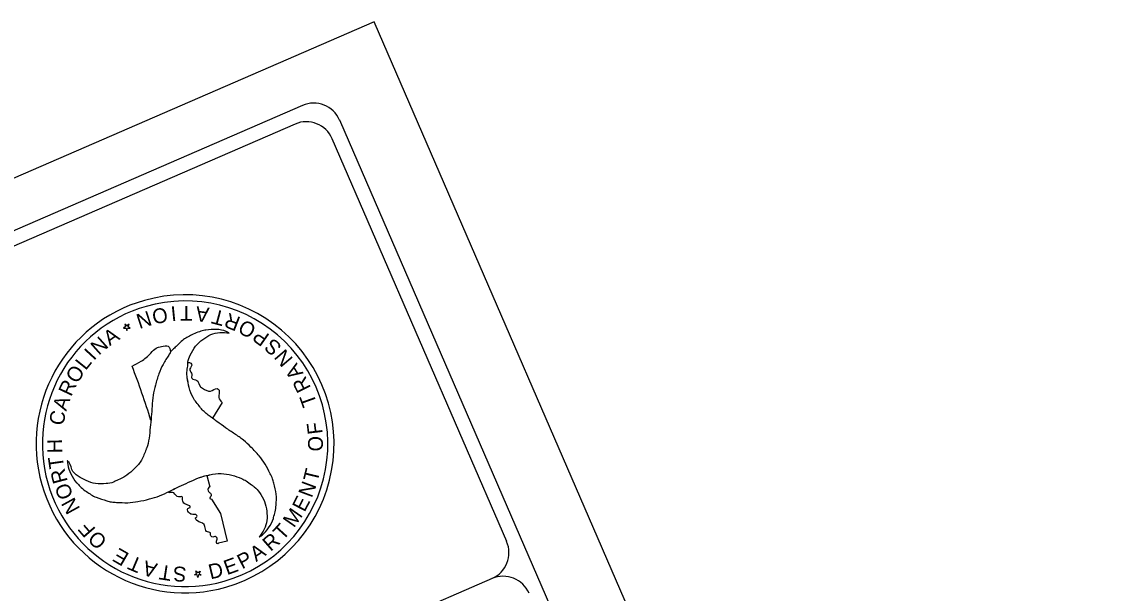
# Model space of a CAD drawing. Extents: x 442728 to 492797, y 479541 to 511293.
# Drawn here: x 478444 to 484269, y 508264 to 511293 of the extents above; entities that cross this region are included whole.
import ezdxf

# ---------------------------------------------------------------- set-up
doc = ezdxf.new("R2010")
doc.units = 0
doc.layers.add('Sheet Plot Border Outside CELL', color=7, linetype='Continuous')
doc.layers.add('Sheet Title CELL', color=7, linetype='Continuous')

msp = doc.modelspace()

# ---------------------------------------------------------------- linework, layer by layer
at = {"layer": 'Sheet Plot Border Outside CELL'}
msp.add_lwpolyline([(465175.4, 504729.3), (475224.7, 481554), (490362.8, 488118.1), (480313.5, 511293.4)], close=True, dxfattribs=at)
at = {"layer": 'Sheet Title CELL'}
for p, q in [((479093.7, 509815.9), (479093.7, 509815.9)), ((479001.2, 509681.9), (478990.1, 509690.2)), ((478990.1, 509690.2), (478994.2, 509677.5)), ((479012.7, 509689.4), (479001.2, 509681.9)), ((479008.1, 509676.6), (479012.7, 509689.4)), ((478994.2, 509677.5), (478983.3, 509669.5)), ((478983.3, 509669.5), (478996.6, 509668.9)), ((478996.6, 509668.9), (479000.3, 509655.9)), ((479000.3, 509655.9), (479004.9, 509668.9)), ((479004.9, 509668.9), (479018.6, 509668.6)), ((479018.6, 509668.6), (479008.1, 509676.6)), ((479506.3, 509274.6), (479455.2, 509191.1)), ((479128.5, 509178.9), (479128.5, 509178.9)), ((479455.2, 509191.1), (479455.2, 509191.1)), ((478684.5, 508964.8), (478686.5, 508963.9)), ((478684.5, 508964.8), (478686.5, 508963.9)), ((479425.4, 508888), (479441.8, 508827.7)), ((479450.4, 508761.4), (479498.3, 508685.6)), ((479498.3, 508685.6), (479533.8, 508539.7)), ((479533.8, 508539.7), (479487.6, 508528.3)), ((480940, 508340.4), (478738.1, 507385.7)), ((479360, 508360), (479370.9, 508368)), ((479373.2, 508359.8), (479360, 508360)), ((479370.9, 508368), (479367.2, 508381)), ((479367.2, 508381), (479378.2, 508372.5)), ((479377, 508346.5), (479373.2, 508359.8)), ((479381.9, 508359.4), (479377, 508346.5)), ((479378.2, 508372.5), (479389.6, 508380.1)), ((479395.6, 508359.1), (479381.9, 508359.4)), ((479389.6, 508380.1), (479384.8, 508367)), ((479384.8, 508367), (479395.6, 508359.1))]:
    msp.add_line(p, q, dxfattribs=at)
for points in [[(479933.3, 510850.6), (465758.6, 504704.2)], [(479894.3, 510752), (477692.4, 509797.2)], [(488962.7, 490404.9), (480130.8, 510772.7)], [(481017.9, 508537.8), (480091.6, 510674)]]:
    msp.add_lwpolyline(points, dxfattribs=at)
for centre, radius, start, end in [((479992.4, 510712.8), 150, 23.44243, 113.44243), ((479953.4, 510614.1), 150, 23.44243, 113.44243), ((479310, 509055.4), 790.8, 105.86356, 285.86356), ((479310, 509055.4), 790.8, 285.86356, 105.86356), ((479310, 509055.4), 757.8, 285.86356, 105.86356), ((479310, 509055.4), 757.8, 105.86356, 285.86356), ((475141.1, 507961.2), 4169.2, 16.98111, 21.18712), ((475141.1, 507961.2), 4169.2, 11.54205, 11.64165), ((480879.5, 508477.8), 150, 293.44243, 23.44243), ((480998.9, 508202.5), 150, 23.44243, 113.44243)]:
    msp.add_arc(centre, radius, start, end, dxfattribs=at)
for points in [[(479543.5, 509642.6), (479528, 509650.9), (479476.4, 509662), (479420.3, 509658.5), (479415, 509657.7), (479385.8, 509649.9), (479352.8, 509636.4), (479301.2, 509608.1), (479257.7, 509567.2), (479239.4, 509550.1), (479223.5, 509526.5), (479193, 509476.9), (479170.8, 509427), (479152.4, 509366.7), (479140.2, 509312.8), (479134.6, 509255.4), (479130.4, 509198.2), (479124.8, 509143), (479118.4, 509084.9), (479104.9, 509030.6), (479103, 509026), (479078.7, 508969.3), (479042, 508924.3), (479001.2, 508888.8), (478978.2, 508874.5), (478947.2, 508860.8), (478929.7, 508852.2), (478890.6, 508844), (478834.6, 508844.7), (478784.6, 508860.4), (478742.2, 508883.7), (478708.5, 508919.7), (478686.5, 508963.9), (478684.5, 508964.8)], [(479702.7, 508560.4), (479718.3, 508570.7), (479753.5, 508609.7), (479778.7, 508659.8), (479779.8, 508664.7), (479788.7, 508694.3), (479792.9, 508729.1), (479794.1, 508788.4), (479780.6, 508846), (479774.9, 508870.4), (479762.1, 508896.7), (479734.6, 508946.9), (479702.9, 508991), (479659.6, 509037.7), (479619.5, 509075), (479572.3, 509108.4), (479524.4, 509140.6), (479479.2, 509173.6), (479433.1, 509208), (479392.1, 509246.8), (479388.6, 509251.4), (479352.3, 509300.5), (479331.7, 509354.1), (479321.6, 509406.8), (479319.6, 509435.2), (479324.2, 509467.9), (479325.1, 509487.9), (479337.5, 509525.8), (479366.1, 509573.2), (479404.7, 509609), (479446.4, 509634.5), (479494.2, 509645.6), (479543.5, 509642.6)], [(479028.6, 509468), (479076.2, 509493.2), (479128.4, 509536.8), (479156.3, 509563.2), (479184.6, 509570.8), (479220, 509573.8), (479232.6, 509542.3)], [(479232.9, 509542.1), (479223.5, 509526.5), (479193, 509476.9), (479170.8, 509427), (479152.4, 509366.7), (479140.2, 509312.8), (479134.6, 509255.4), (479130.4, 509198.2), (479128.5, 509178.9)], [(479455.2, 509191.1), (479433.1, 509208), (479392.1, 509246.8), (479388.6, 509251.4), (479352.3, 509300.5), (479331.7, 509354.1), (479321.6, 509406.8), (479319.6, 509435.2), (479324.2, 509467.9), (479325.2, 509486.5)], [(479325.5, 509486.4), (479340.8, 509483.1), (479345, 509471.9), (479334.7, 509447.3), (479346.6, 509424.1), (479343.3, 509411), (479345.2, 509403.5), (479372.5, 509392), (479384.9, 509369.2), (479425.2, 509338), (479444.4, 509334.7), (479480.1, 509348), (479490, 509340.4), (479491.6, 509328.1), (479489, 509301.1), (479506.3, 509274.6)], [(478686.5, 508963.9), (478686.8, 508945.5), (478703.2, 508895.5), (478734.3, 508848.8), (478738.1, 508845), (478758.9, 508823.2), (478786.9, 508801.6), (478837.7, 508771.5), (478894.6, 508753.6), (478918.7, 508746.8), (478946.6, 508744.7), (479005.1, 508743), (479059.4, 508749), (479121, 508762.8), (479174, 508778.8), (479225.8, 508803.1), (479277.9, 508828.1), (479328.9, 508851.1), (479381.6, 508874.1), (479435.8, 508889.8), (479440.6, 508890.9), (479501.3, 508897.7), (479558.7, 508888.7), (479609.9, 508870.6), (479634.6, 508858.3), (479661.7, 508838.5), (479677.3, 508827.3), (479704.7, 508797.8), (479731.6, 508749.2), (479743.2, 508697.4), (479744.5, 508649.1), (479730.3, 508602.1), (479702.7, 508560.4)], [(479224.5, 508802.5), (479225.8, 508803.1), (479277.9, 508828.1), (479328.9, 508851.1), (479381.6, 508874.1), (479425.4, 508887.8)], [(479441.8, 508827.7), (479432.4, 508818.7), (479432.4, 508806), (479445.2, 508792.6), (479447.9, 508780.4), (479442.2, 508764.6), (479450.4, 508761.4)], [(479487.6, 508528.3), (479483.8, 508525.5), (479476.7, 508531.8), (479479.4, 508555.7), (479467, 508563.9), (479457.9, 508560.8), (479446.3, 508566.7), (479445, 508582.2), (479424.3, 508590.7), (479417.9, 508602.1), (479410.6, 508627.8), (479371.3, 508649.5), (479365.9, 508661.8), (479373.1, 508667.3), (479372.4, 508675.6), (479343.5, 508681.5), (479338.9, 508683.9), (479322.6, 508705.1), (479325.3, 508712.7), (479336.1, 508717.7), (479337.4, 508721.7), (479329.5, 508728), (479313, 508734.8), (479297.3, 508751.5), (479293.6, 508774.6), (479274.3, 508773.2), (479249.3, 508794.4), (479237.1, 508796.8), (479225.9, 508795.1)]]:
    msp.add_spline(points, degree=3, dxfattribs=at)

# ---------------------------------------------------------------- texts
for s, height, rotation, p in [('N', 78.9, 198.07169, (479115.7, 509762.5)), ('O', 78.6, 190.82368, (479209.1, 509781.2)), ('I', 79, 185.68805, (479259.4, 509786.8)), ('T', 78.7, 180.03814, (479348.4, 509787.2)), ('A', 79, 172.95372, (479441.3, 509776.8)), ('T', 78.6, 164.86668, (479528, 509754.9)), ('R', 79, 158.76689, (479609.7, 509724.3)), ('O', 79, 151.57778, (479693.9, 509679.5)), ('N', 78.8, 41.7589, (478852.1, 509521.6)), ('A', 78.9, 34.32692, (478910.1, 509572.7)), ('P', 78.8, 144.88579, (479763.3, 509631.5)), ('I', 79, 47.459, (478825.6, 509493.7)), ('S', 78.5, 137.69394, (479828.1, 509573.1)), ('L', 78.6, 51.44834, (478782, 509441.3)), ('N', 78.6, 130.48347, (479887.3, 509506.4)), ('O', 79, 57.68202, (478737.2, 509370.3)), ('A', 78.6, 123.45184, (479939.9, 509429.5)), ('R', 78.8, 64.80162, (478704.9, 509302.2)), ('R', 78.9, 116.69871, (479980.1, 509352.2)), ('A', 78.8, 71.16557, (478678.9, 509225.6)), ('T', 78.6, 109.74209, (480011.2, 509268.4)), ('C', 78.6, 78.6626, (478663, 509148.5)), ('F', 78.8, 96.83286, (480040.7, 509109.9)), ('H', 78.7, 91.00495, (478658.2, 509005.8)), ('O', 78.8, 89.66763, (480041.4, 509014.6)), ('T', 79, 98.08967, (478668.5, 508929.3)), ('R', 78.9, 104.7393, (478687.8, 508856.3)), ('T', 78.7, 76.36394, (480012.8, 508848.8)), ('O', 79, 111.34923, (478718.2, 508778.7)), ('N', 79, 69.52194, (479982.4, 508765.2)), ('N', 78.9, 118.84734, (478755, 508710.9)), ('E', 78.6, 62.5504, (479944.1, 508689.2)), ('M', 78.6, 55.08363, (479888, 508606)), ('T', 78.8, 47.84858, (479828.9, 508538.8)), ('F', 79, 130.93428, (478839.1, 508602.5)), ('O', 78.9, 138.08112, (478900.9, 508546.5)), ('R', 78.8, 41.19805, (479764, 508480.9)), ('A', 78.7, 34.12941, (479687.3, 508427.6)), ('E', 78.6, 150.0205, (479018.4, 508470.7)), ('T', 78.7, 157.13613, (479089.4, 508440.5)), ('P', 78.9, 27.53684, (479612.6, 508388.6)), ('A', 79.1, 164.19135, (479167.8, 508418.2)), ('T', 79, 171.24366, (479243.8, 508405.4)), ('S', 78.8, 177.61981, (479318.8, 508402.1)), ('D', 78.9, 13.71656, (479444.9, 508335.6)), ('E', 78.5, 20.00445, (479532.7, 508357.9))]:
    msp.add_text(s, height=height, rotation=rotation, dxfattribs=at).set_placement(p)

doc.saveas('drawing.dxf')
